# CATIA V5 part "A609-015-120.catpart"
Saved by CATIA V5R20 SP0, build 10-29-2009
Part number: A609-015-120
Source: Unknown
Property "ARTICLENO": "A609-015-120"
Property "B": "12.500"
Property "BOMINFO": "A609-015-120"
Property "CODE": "A609-015-120"
Property "D": "18.000"
Property "D1": "11.000"
Property "FORM": "A"
Property "L": "120.000"
Property "L1": "25.000"
Property "L2": "70.000"
Property "LINA": "A609-015-120"
Property "NB": "A609-015-120"
Property "NBSYN": "$CODE."
Property "NN": "A609"
Property "NT": "VDI 3357 E-Type Wear Plates, self-lubricating"
Property "S": "15.000"
Property "SUPPLIER": "CF"
Property "T": "10.500"
Property "W": "25.000"
Bounding box of the stored display mesh (mm): x 0 to 120, y 0 to 15, z 0 to 25
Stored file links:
  C:\Users\Utente\Desktop\3D files A609\A609-015-120.catpart
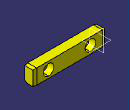
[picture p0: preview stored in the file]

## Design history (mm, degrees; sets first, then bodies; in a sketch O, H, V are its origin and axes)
Body1 "Geometry.1" (main body)
  Solid1 "A609-015-120.catpart": solid without history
